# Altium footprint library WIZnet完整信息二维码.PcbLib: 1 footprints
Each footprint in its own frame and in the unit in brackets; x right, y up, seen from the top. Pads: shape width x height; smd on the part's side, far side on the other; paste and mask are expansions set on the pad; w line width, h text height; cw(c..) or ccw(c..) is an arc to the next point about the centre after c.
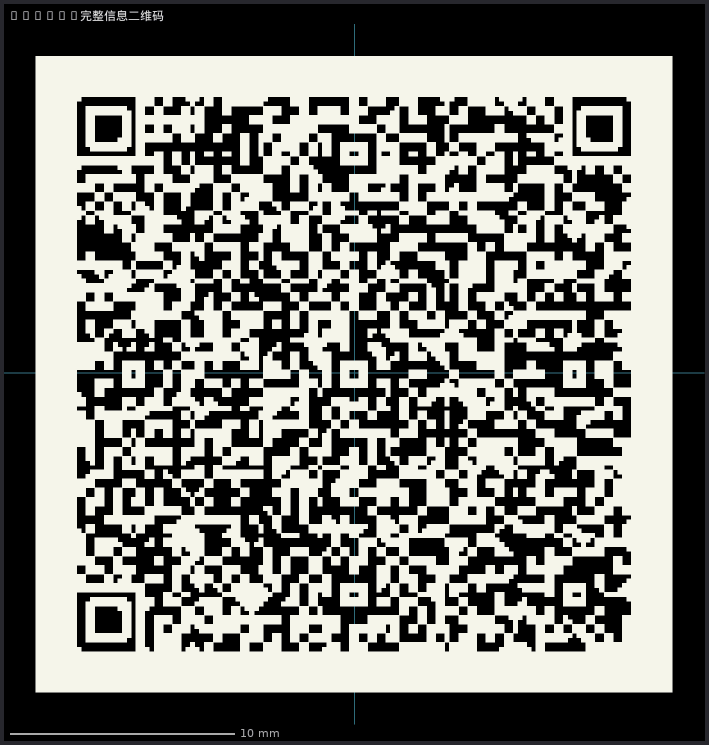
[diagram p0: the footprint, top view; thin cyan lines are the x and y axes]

## WIZnet完整信息二维码 [mm] "WIZnet完整信息二维码"
Top Overlay:
  drawing of 17208 lines, arcs and shapes, not listed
